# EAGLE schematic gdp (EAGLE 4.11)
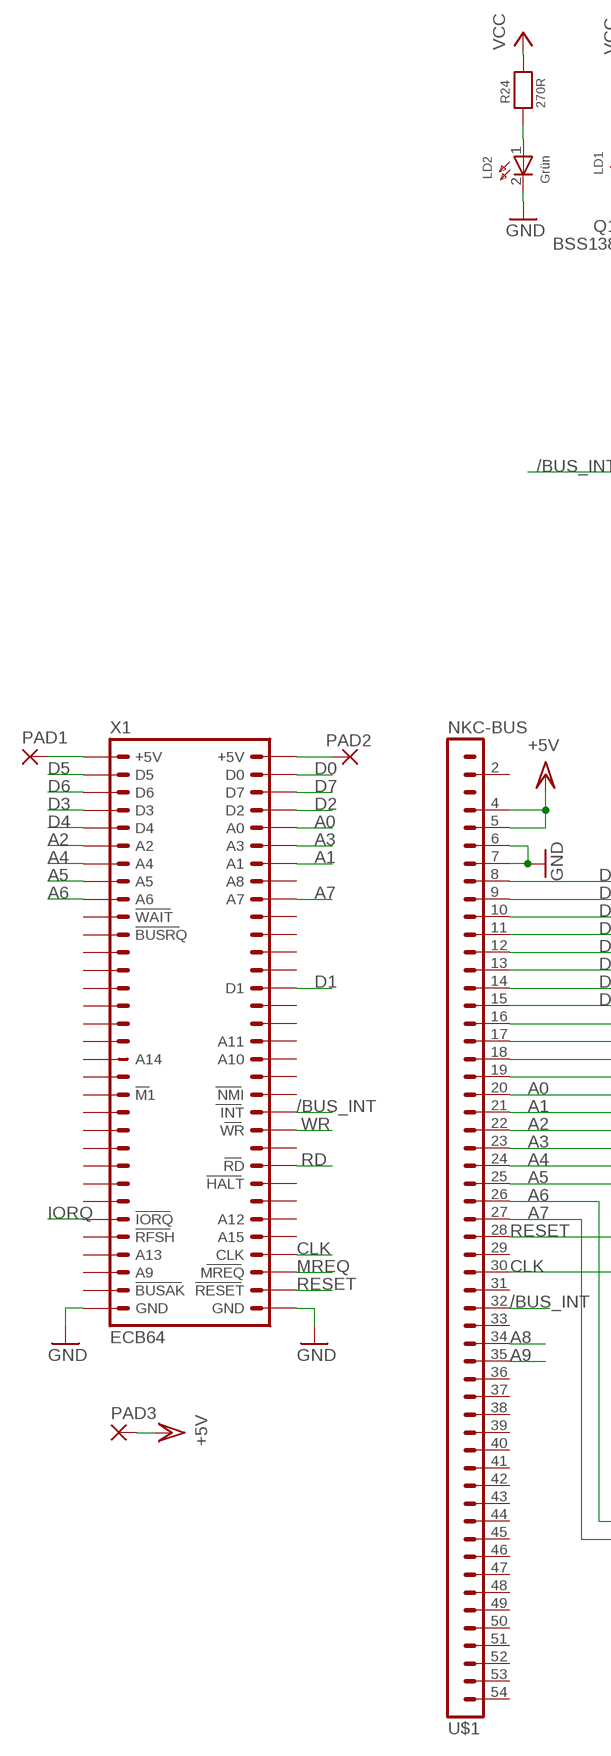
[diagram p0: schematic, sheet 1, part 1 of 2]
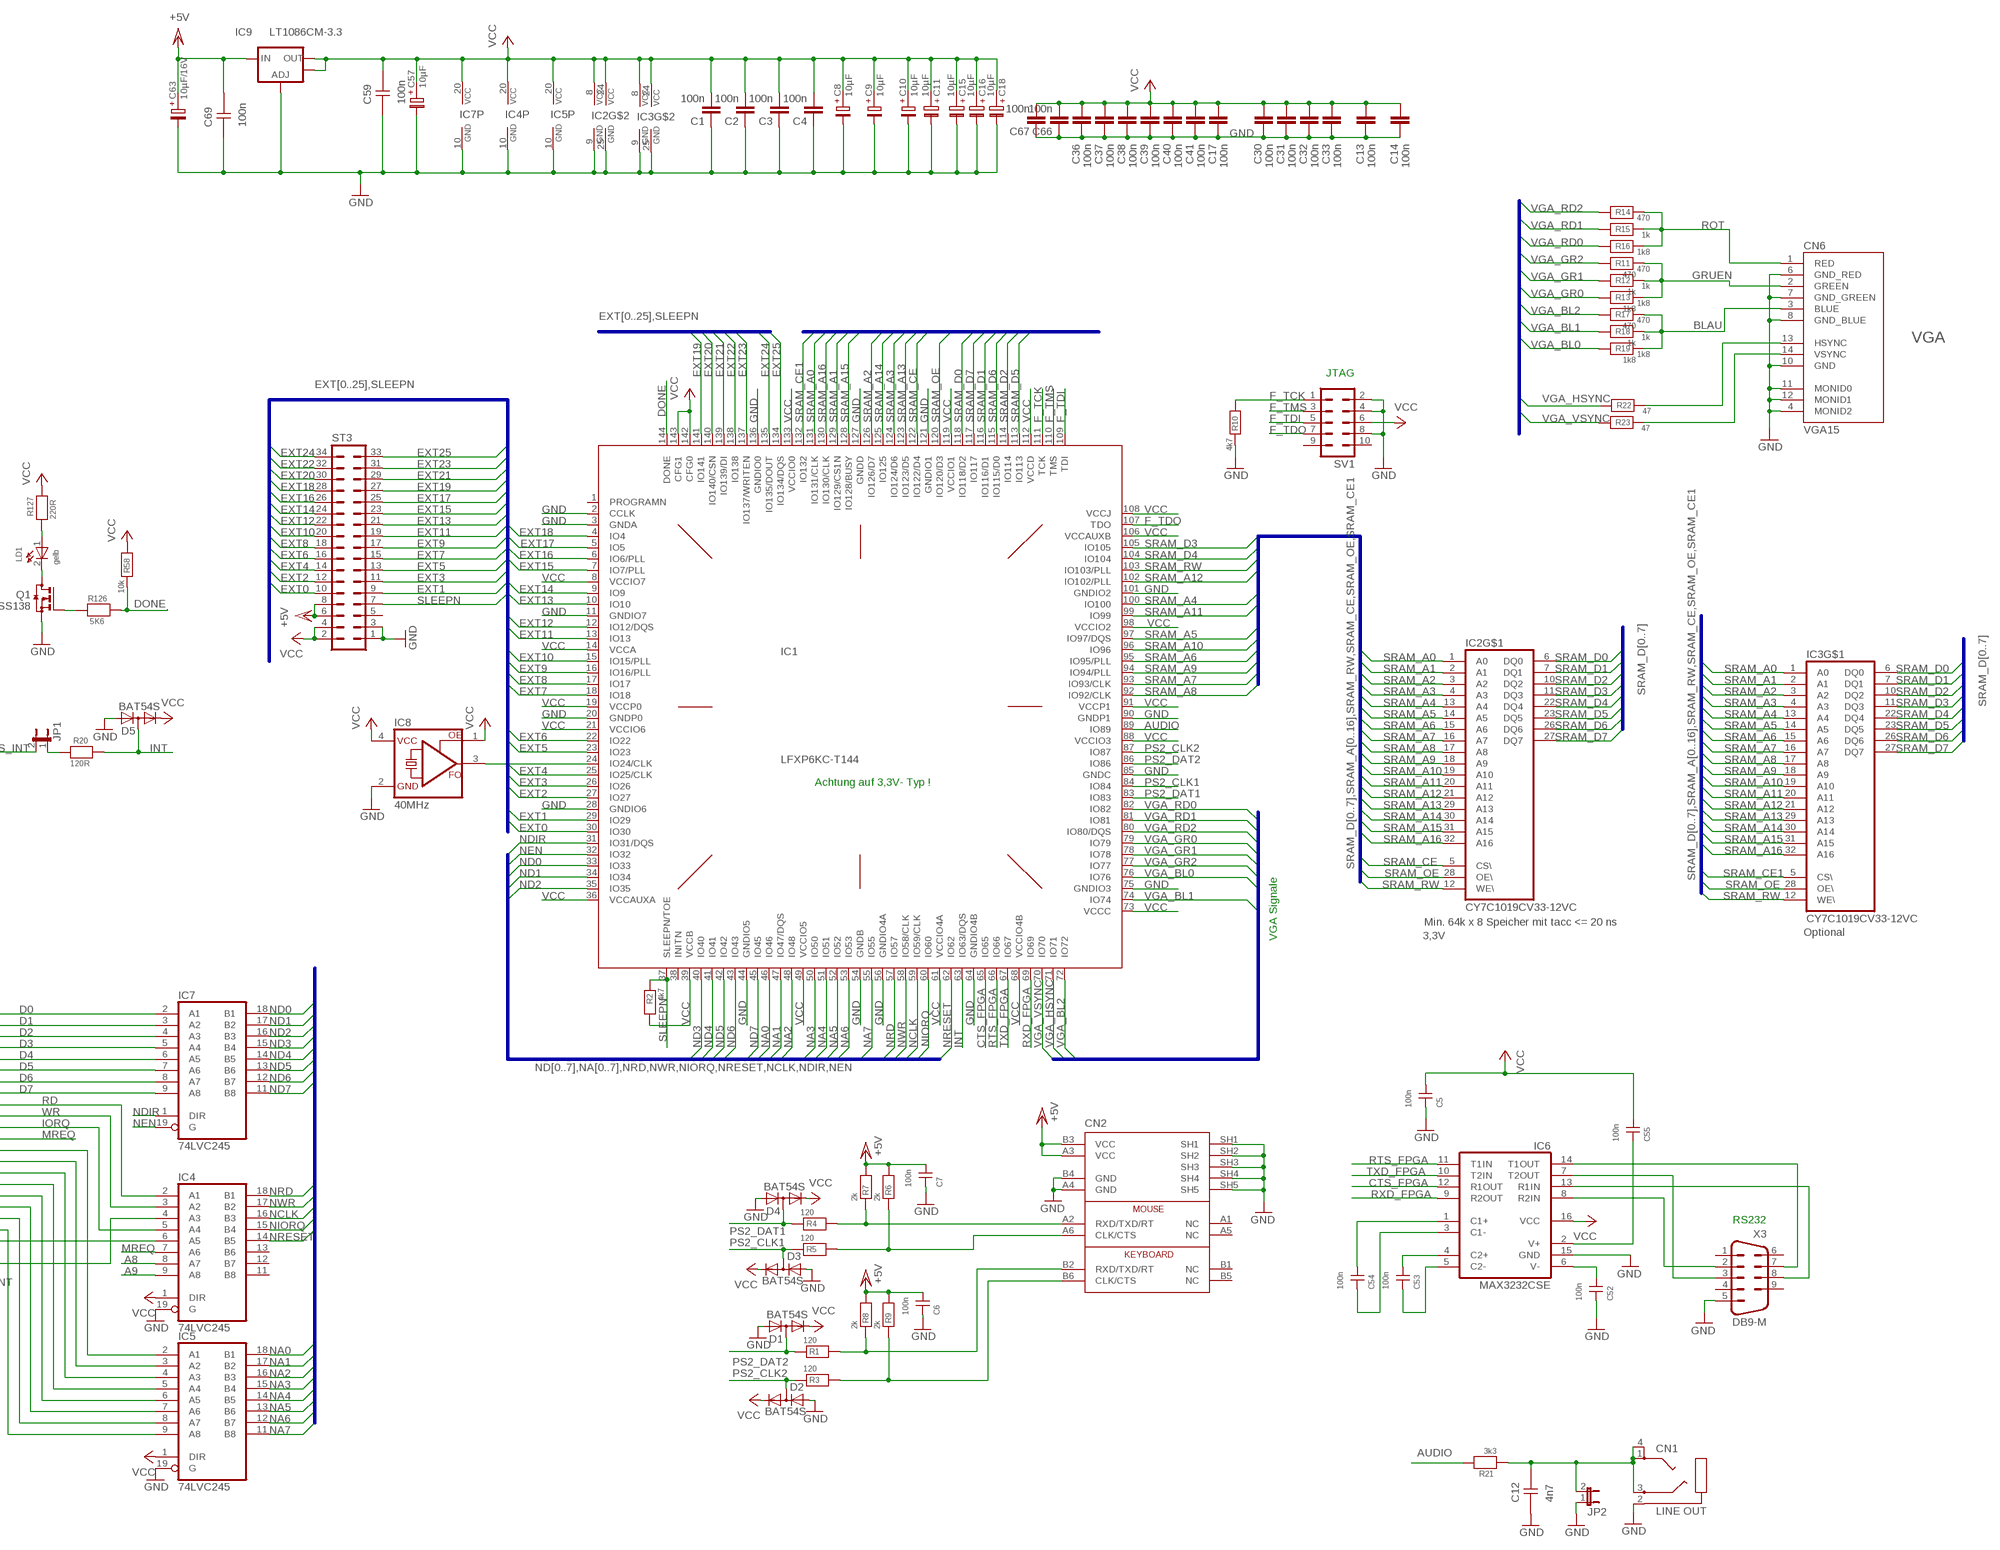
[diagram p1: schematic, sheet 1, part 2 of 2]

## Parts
C1  100n  C-EUC0805K  [C0805K]
C2  100n  C-EUC0805K  [C0805K]
C3  100n  C-EUC0805K  [C0805K]
C4  100n  C-EUC0805K  [C0805K]
C5  100n  CAP0805  [0805]
C6  100n  CAP0805  [0805]
C7  100n  CAP0805  [0805]
C8  10µF  CAPP6032  [TANT_B]
C9  10µF  CAPP6032  [TANT_B]
C10  10µF  CAPP6032  [TANT_B]
C11  10µF  CAPP6032  [TANT_B]
C12  4n7  CAP1206  [0805]
C13  100n  C-EUC0805K  [C0805K]
C14  100n  C-EUC0805K  [C0805K]
C15  10µF  CAPP6032  [TANT_B]
C16  10µF  CAPP6032  [TANT_B]
C17  100n  C-EUC0805K  [C0805K]
C18  10µF  CAPP6032  [TANT_B]
C30  100n  C-EUC0805K  [C0805K]
C31  100n  C-EUC0805K  [C0805K]
C32  100n  C-EUC0805K  [C0805K]
C33  100n  C-EUC0805K  [C0805K]
C36  100n  C-EUC0805K  [C0805K]
C37  100n  C-EUC0805K  [C0805K]
C38  100n  C-EUC0805K  [C0805K]
C39  100n  C-EUC0805K  [C0805K]
C40  100n  C-EUC0805K  [C0805K]
C41  100n  C-EUC0805K  [C0805K]
C52  100n  CAP0805  [0805]
C53  100n  CAP0805  [0805]
C54  100n  CAP0805  [0805]
C55  100n  CAP0805  [0805]
C57  10µF  CAPP6032  [TANT_B]
C59  100n  CAP1206  [0805]
C63  10µF/16V  CAPP6032@2  [TANT_C]
C66  100n  C-EUC0805K  [C0805K]
C67  100n  C-EUC0805K  [C0805K]
C69  100n  CAP1206  [0805]
CN1  LINE OUT  BUCHSE3,5MM  [KLINKE3,5]
CN2  MINIDIN_6POL_DOUBLE  [MINIDIN_6POL_DOUBLE]
CN6  VGA15  VGA15_2  [D-HD15F2]
D1  BAT54S  BAS70-04  [SOT23]
D2  BAT54S  BAS70-04  [SOT23]
D3  BAT54S  BAS70-04  [SOT23]
D4  BAT54S  BAS70-04  [SOT23]
D5  BAT54S  BAS70-04  [SOT23]
IC1  LFXP6KC-T144  [TQFP144]
IC2  CY7C1019CV33-12VC  CY7C1019B  [SOJ32/4]
IC3  CY7C1019CV33-12VC  CY7C1019B  [SOJ32/4]
IC4  74LVC245  74AC245DW  [SO20W]
IC5  74LVC245  74AC245DW  [SO20W]
IC6  MAX3232CSE  MAX3232CWE  [SO16L]
IC7  74LVC245  74AC245DW  [SO20W]
IC8  40MHz  SMDOSZI  [CRYSTAL]
IC9  LT1086CM-3.3  LT1086CM  [3LEAD_DD]
JP1  JP1E  [JP1]
JP2  JP1E  [JP1]
LD1  gelb  LED0603  [0603LED]
LD2  Grün  LED0603  [0603LED]
PAD1  SMD2  [SMD2]
PAD2  SMD2  [SMD2]
PAD3  SMD2  [SMD2]
Q1  BSS138  BSS123  [SOT23]
R1  120  REU0805  [0805]
R2  4k7  REU0805  [0805]
R3  120  REU0805  [0805]
R4  120  REU0805  [0805]
R5  120  REU0805  [0805]
R6  2k  REU0805  [0805]
R7  2k  REU0805  [0805]
R8  2k  REU0805  [0805]
R9  2k  REU0805  [0805]
R10  4k7  REU0805  [0805]
R11  470  REU0805  [0805]
R12  1k  REU0805  [0805]
R13  1k8  REU0805  [0805]
R14  470  REU0805  [0805]
R15  1k  REU0805  [0805]
R16  1k8  REU0805  [0805]
R17  470  REU0805  [0805]
R18  1k  REU0805  [0805]
R19  1k8  REU0805  [0805]
R20  120R  REU0805  [0805]
R21  3k3  REU0805  [0805]
R22  47  REU0805  [0805]
R23  47  REU0805  [0805]
R24  270R  REU0805  [0805]
R58  10k  REU0805  [0805]
R126  5K6  REU0805  [0805]
R127  220R  REU0805  [0805]
ST3  MA17-2  [MA17-2]
SV1  MA05-2  [MA05-2]
U$1  NKC-BUS  [NKC-BUS]
X1  ECB64  [ML64ECB]
X3  DB9-M  M09HP  [M09HP]

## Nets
/BUS_INT: JP1.2 U$1.32 X1.INT
A0: IC5.2(A1) U$1.20 X1.A0
A1: IC5.3(A2) U$1.21 X1.A1
A2: IC5.4(A3) U$1.22 X1.A2
A3: IC5.5(A4) U$1.23 X1.A3
A4: IC5.6(A5) U$1.24 X1.A4
A5: IC5.7(A6) U$1.25 X1.A5
A6: IC5.8(A7) U$1.26 X1.A6
A7: IC5.9(A8) U$1.27 X1.A7
A8: IC4.8(A7) U$1.34
A9: IC4.9(A8) U$1.35
AUDIO: IC1.89(IO89) R21.2
BLAU: CN6.3(BLUE) R17.1 R18.1 R19.1
CLK: IC4.4(A3) U$1.30 X1.CLK
CTS_FPGA: IC1.65(IO65) IC6.12(R1OUT)
D0: IC7.2(A1) U$1.8 X1.D0
D1: IC7.3(A2) U$1.9 X1.D1
D2: IC7.4(A3) U$1.10 X1.D2
D3: IC7.5(A4) U$1.11 X1.D3
D4: IC7.6(A5) U$1.12 X1.D4
D5: IC7.7(A6) U$1.13 X1.D5
D6: IC7.8(A7) U$1.14 X1.D6
D7: IC7.9(A8) U$1.15 X1.D7
DONE: IC1.144(DONE) R58.1 R126.1
EXT0: IC1.30(IO30) ST3.10
EXT1: IC1.29(IO29) ST3.9
EXT2: IC1.27(IO27) ST3.12
EXT3: IC1.26(IO26) ST3.11
EXT4: IC1.25(IO25/CLK) ST3.14
EXT5: IC1.23(IO23) ST3.13
EXT6: IC1.22(IO22) ST3.16
EXT7: IC1.18(IO18) ST3.15
EXT8: IC1.17(IO17) ST3.18
EXT9: IC1.16(IO16/PLL) ST3.17
EXT10: IC1.15(IO15/PLL) ST3.20
EXT11: IC1.13(IO13) ST3.19
EXT12: IC1.12(IO12/DQS) ST3.22
EXT13: IC1.10(IO10) ST3.21
EXT14: IC1.9(IO9) ST3.24
EXT15: IC1.7(IO7/PLL) ST3.23
EXT16: IC1.6(IO6/PLL) ST3.26
EXT17: IC1.5(IO5) ST3.25
EXT18: IC1.4(IO4) ST3.28
EXT19: IC1.141(IO141) ST3.27
EXT20: IC1.140(IO140/CSN) ST3.30
EXT21: IC1.139(IO139/DI) ST3.29
EXT22: IC1.138(IO138) ST3.32
EXT23: IC1.137(IO137/WRITEN) ST3.31
EXT24: IC1.135(IO135/DOUT) ST3.34
EXT25: IC1.134(IO134/DQS) ST3.33
F_TCK: IC1.111(TCK) R10.2 SV1.1
F_TDI: IC1.109(TDI) SV1.5
F_TDO: IC1.107(TDO) SV1.7
F_TMS: IC1.110(TMS) SV1.3
GND: C1.1 C2.1 C3.1 C4.1 C5.1 C6.1 C7.1 C8.2(-) C9.2(-) C10.2(-) C11.2(-) C12.1 C13.1 C14.1 C15.2(-) C16.2(-) C17.1 C18.2(-) C30.1 C31.1 C32.1 C33.1 C36.1 C37.1 C38.1 C39.1 C40.1 C41.1 C52.1 C57.2(-) C59.1 C63.2(-) C66.1 C67.1 C69.1 CN1.2(GND) CN2.A4(GND) CN2.B4(GND) CN2.SH1 CN2.SH2 CN2.SH3 CN2.SH4 CN2.SH5 CN6.4(MONID2) CN6.6(GND_RED) CN6.7(GND_GREEN) CN6.8(GND_BLUE) CN6.10(GND) CN6.11(MONID0) CN6.12(MONID1) D1.1(A) D2.1(A) D3.1(A) D4.1(A) D5.1(A) IC1.2(CCLK) IC1.3(GNDA) IC1.11(GNDIO7) IC1.20(GNDP0) IC1.28(GNDIO6) IC1.44(GNDIO5) IC1.54(GNDB) IC1.56(GNDIO4A) IC1.64(GNDIO4B) IC1.75(GNDIO3) IC1.85(GNDC) IC1.90(GNDP1) IC1.101(GNDIO2) IC1.121(GNDIO1) IC1.127(GNDD) IC1.136(GNDIO0) IC2.9(GND) IC2.25(GND1) IC3.9(GND) IC3.25(GND1) IC4.10(GND) IC4.19(G) IC5.10(GND) IC5.19(G) IC6.15(GND) IC7.10(GND) IC8.2(GND) IC9.1(ADJ) JP2.1 LD2.2(K) Q1.2(S) R10.1 ST3.1 ST3.3 SV1.2 SV1.4 SV1.8 U$1.6 U$1.7 X1.GND X1.GND@1(GND) X3.5
GRUEN: CN6.2(GREEN) R11.1 R12.1 R13.1
INT: D5.3(AC) IC1.63(IO63/DQS) R20.2
IORQ: IC4.5(A4) U$1.18 X1.IORQ
MREQ: IC4.7(A6) U$1.19 X1.MREQ
N$1: IC1.24(IO24/CLK) IC8.3(FO)
N$2: PAD1.1(P) X1.+5V
N$3: LD2.1(A) R24.1
N$4: IC6.14(T1OUT) X3.7
N$5: IC6.13(R1IN) X3.8
N$7: CN2.A2(RXD/TXD/RT) R4.2 R7.1
N$8: C54.2 IC6.1(C1+)
N$9: CN2.A6(CLK/CTS) R5.2 R6.1
N$10: CN2.B2(RXD/TXD/RT) R1.2 R8.1
N$11: CN2.B6(CLK/CTS) R3.2 R9.1
N$18: PAD2.1(P) X1.+5V@1(+5V)
N$20: C54.1 IC6.3(C1-)
N$22: C53.2 IC6.4(C2+)
N$23: C53.1 IC6.5(C2-)
N$27: JP1.1 R20.1
N$28: C12.2 CN1.1(LEFT1) CN1.3(RIGHT) CN1.4(LEFT2) JP2.2 R21.1
N$30: CN6.13(HSYNC) R22.1
N$36: CN6.14(VSYNC) R23.1
N$80: LD1.1(A) R127.1
N$89: LD1.2(K) Q1.3(D)
N$92: Q1.1(G) R126.2
NA0: IC1.46(IO46) IC5.18(B1)
NA1: IC1.47(IO47/DQS) IC5.17(B2)
NA2: IC1.48(IO48) IC5.16(B3)
NA3: IC1.50(IO50) IC5.15(B4)
NA4: IC1.51(IO51) IC5.14(B5)
NA5: IC1.52(IO52) IC5.13(B6)
NA6: IC1.53(IO53) IC5.12(B7)
NA7: IC1.55(IO55) IC5.11(B8)
NCLK: IC1.59(IO59/CLK) IC4.16(B3)
ND0: IC1.33(IO33) IC7.18(B1)
ND1: IC1.34(IO34) IC7.17(B2)
ND2: IC1.35(IO35) IC7.16(B3)
ND3: IC1.40(IO40) IC7.15(B4)
ND4: IC1.41(IO41) IC7.14(B5)
ND5: IC1.42(IO42) IC7.13(B6)
ND6: IC1.43(IO43) IC7.12(B7)
ND7: IC1.45(IO45) IC7.11(B8)
NDIR: IC1.31(IO31/DQS) IC7.1(DIR)
NEN: IC1.32(IO32) IC7.19(G)
NIORQ: IC1.60(IO60) IC4.15(B4)
NRD: IC1.57(IO57) IC4.18(B1)
NRESET: IC1.62(IO62) IC4.14(B5)
NWR: IC1.58(IO58/CLK) IC4.17(B2)
PS2_CLK1: D3.3(AC) IC1.84(IO84) R5.1
PS2_CLK2: D2.3(AC) IC1.87(IO87) R3.1
PS2_DAT1: D4.3(AC) IC1.83(IO83) R4.1
PS2_DAT2: D1.3(AC) IC1.86(IO86) R1.1
RD: IC4.2(A1) U$1.16 X1.RD
RESET: IC4.6(A5) U$1.28 X1.RESET
ROT: CN6.1(RED) R14.1 R15.1 R16.1
RTS_FPGA: IC1.66(IO66) IC6.11(T1IN)
RXD: IC6.8(R2IN) X3.2
RXD_FPGA: IC1.69(IO69) IC6.9(R2OUT)
SLEEPN: IC1.37(SLEEPN/TOE) R2.1 ST3.7
SRAM_A0: IC1.131(IO131/CLK) IC2.1(A0) IC3.1(A0)
SRAM_A1: IC1.129(IO129/CS1N) IC2.2(A1) IC3.2(A1)
SRAM_A2: IC1.126(IO126/D7) IC2.3(A2) IC3.3(A2)
SRAM_A3: IC1.124(IO124/D6) IC2.4(A3) IC3.4(A3)
SRAM_A4: IC1.100(IO100) IC2.13(A4) IC3.13(A4)
SRAM_A5: IC1.97(IO97/DQS) IC2.14(A5) IC3.14(A5)
SRAM_A6: IC1.95(IO95/PLL) IC2.15(A6) IC3.15(A6)
SRAM_A7: IC1.93(IO93/CLK) IC2.16(A7) IC3.16(A7)
SRAM_A8: IC1.92(IO92/CLK) IC2.17(A8) IC3.17(A8)
SRAM_A9: IC1.94(IO94/PLL) IC2.18(A9) IC3.18(A9)
SRAM_A10: IC1.96(IO96) IC2.19(A10) IC3.19(A10)
SRAM_A11: IC1.99(IO99) IC2.20(A11) IC3.20(A11)
SRAM_A12: IC1.102(IO102/PLL) IC2.21(A12) IC3.21(A12)
SRAM_A13: IC1.123(IO123/D5) IC2.29(A13) IC3.29(A13)
SRAM_A14: IC1.125(IO125) IC2.30(A14) IC3.30(A14)
SRAM_A15: IC1.128(IO128/BUSY) IC2.31(A15) IC3.31(A15)
SRAM_A16: IC1.130(IO130/CLK) IC2.32(A16) IC3.32(A16)
SRAM_CE: IC1.122(IO122/D4) IC2.5(CS\)
SRAM_CE1: IC1.132(IO132) IC3.5(CS\)
SRAM_D0: IC1.118(IO118/D2) IC2.6(DQ0) IC3.6(DQ0)
SRAM_D1: IC1.116(IO116/D1) IC2.7(DQ1) IC3.7(DQ1)
SRAM_D2: IC1.114(IO114) IC2.10(DQ2) IC3.10(DQ2)
SRAM_D3: IC1.105(IO105) IC2.11(DQ3) IC3.11(DQ3)
SRAM_D4: IC1.104(IO104) IC2.22(DQ4) IC3.22(DQ4)
SRAM_D5: IC1.113(IO113) IC2.23(DQ5) IC3.23(DQ5)
SRAM_D6: IC1.115(IO115/D0) IC2.26(DQ6) IC3.26(DQ6)
SRAM_D7: IC1.117(IO117) IC2.27(DQ7) IC3.27(DQ7)
SRAM_OE: IC1.120(IO120/D3) IC2.28(OE\) IC3.28(OE\)
SRAM_RW: IC1.103(IO103/PLL) IC2.12(WE\) IC3.12(WE\)
TXD: IC6.7(T2OUT) X3.3
TXD_FPGA: IC1.67(IO67) IC6.10(T2IN)
V+_IC1: C55.1 IC6.2(V+)
V-_IC1: C52.2 IC6.6(V-)
VCC: C1.2 C2.2 C3.2 C4.2 C5.2 C8.1(+) C9.1(+) C10.1(+) C11.1(+) C13.2 C14.2 C15.1(+) C16.1(+) C17.2 C18.1(+) C30.2 C31.2 C32.2 C33.2 C36.2 C37.2 C38.2 C39.2 C40.2 C41.2 C55.2 C57.1(+) C59.2 C66.2 C67.2 D1.2(C) D2.2(C) D3.2(C) D4.2(C) D5.2(C) IC1.8(VCCIO7) IC1.14(VCCA) IC1.19(VCCP0) IC1.21(VCCIO6) IC1.36(VCCAUXA) IC1.39(VCCB) IC1.49(VCCIO5) IC1.61(VCCIO4A) IC1.68(VCCIO4B) IC1.73(VCCC) IC1.88(VCCIO3) IC1.91(VCCP1) IC1.98(VCCIO2) IC1.106(VCCAUXB) IC1.108(VCCJ) IC1.112(VCCD) IC1.119(VCCIO1) IC1.133(VCCIO0) IC1.142(CFG0) IC1.143(CFG1) IC2.8(VCC) IC2.24(VCC3) IC3.8(VCC) IC3.24(VCC3) IC4.1(DIR) IC4.20(VCC) IC5.1(DIR) IC5.20(VCC) IC6.16(VCC) IC7.20(VCC) IC8.1(OE) IC8.4(VCC) IC9.2(OUT) IC9.2@1(OUT1) R2.2 R24.2 R58.2 R127.2 ST3.2 ST3.4 SV1.6
VCC/2: C6.2 C7.2 C63.1(+) C69.2 CN2.A3(VCC) CN2.B3(VCC) IC9.3(IN) PAD3.1(P) R6.2 R7.2 R8.2 R9.2 ST3.6 ST3.8 U$1.4 U$1.5 ; supply symbol labelled +5V
VGA_BL0: IC1.76(IO76) R19.2
VGA_BL1: IC1.74(IO74) R18.2
VGA_BL2: IC1.72(IO72) R17.2
VGA_GR0: IC1.79(IO79) R13.2
VGA_GR1: IC1.78(IO78) R12.2
VGA_GR2: IC1.77(IO77) R11.2
VGA_HSYNC: IC1.71(IO71) R22.2
VGA_RD0: IC1.82(IO82) R16.2
VGA_RD1: IC1.81(IO81) R15.2
VGA_RD2: IC1.80(IO80/DQS) R14.2
VGA_VSYNC: IC1.70(IO70) R23.2
WR: IC4.3(A2) U$1.17 X1.WR
Unconnected: CN2.A1(NC) CN2.A5(NC) CN2.B1(NC) CN2.B5(NC) CN6.5(NC) CN6.9(NC) CN6.15(NC) IC1.1(PROGRAMN) IC1.38(INITN) IC4.11(B8) IC4.12(B7) IC4.13(B6) ST3.5 SV1.9 SV1.10 U$1.2 U$1.29 U$1.31 U$1.33 U$1.36 U$1.37 U$1.38 U$1.39 U$1.40 U$1.41 U$1.42 U$1.43 U$1.44 U$1.45 U$1.46 U$1.47 U$1.48 U$1.49 U$1.50 U$1.51 U$1.52 U$1.53 U$1.54 X1.10C X1.11C X1.12A X1.12C X1.13A X1.13C X1.14A X1.15A X1.15C X1.16A X1.16C X1.17A X1.19A X1.19C X1.21A X1.22A X1.23A X1.23C X1.24A X1.25A X1.26A X1.26C X1.A8 X1.A9 X1.A10 X1.A11 X1.A12 X1.A13 X1.A14 X1.A15 X1.BUSAK X1.BUSRQ X1.HALT X1.M1 X1.NMI X1.RFSH X1.WAIT X3.1 X3.4 X3.6 X3.9

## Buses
SRAM_D[0..7],SRAM_A[0..16],SRAM_RW,SRAM_CE,SRAM_OE,SRAM_CE1
SRAM_D[0..7]
VGA_RD[0..2],VGA_BL[0..2],VGA_GR[0..2],VGA_VSYNC,VGA_HSYNC
ND[0..7],NA[0..7],NRD,NWR,NIORQ,NRESET,NCLK,NDIR,NEN
EXT[0..25],SLEEPN

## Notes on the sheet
- VGA
- JTAG
- Achtung auf 3,3V- Typ !
- VGA Signale
- Min. 64k x 8 Speicher mit tacc <= 20 ns
- Optional
- 3,3V
- RS232

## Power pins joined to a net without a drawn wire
AGND1: CN6.PAD1(AGND1)
AGND2: CN6.PAD2(AGND2)

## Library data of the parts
C1-C4 C13 C14 C17 C30-C33 C36-C41 C66 C67 = rcl:C-EU: CAPACITOR, European symbol
C5-C7 C52-C55 = DISCRSMD:CAP0805
C8-C11 C15 C16 C18 C57 = DiscrSMD@3:CAPP6032
C12 C59 C69 = DiscrSMD@2:CAP1206
C63 = DiscrSMD@3:CAPP6032@2
CN1 = con-audio:BUCHSE3,5MM: 3,5mm Klinkenbuchse
CN2 = Con-pc2:MINIDIN_6POL_DOUBLE
CN6 = CON-PC:VGA15_2
D1-D5 = diode:BAS70-04: Silicon Schottky Diodes General-purpose diode for high-speed switching
IC1 = lattice:LFXP6KC-T144
IC2 IC3 = cy7c1009b:CY7C1019B
IC4 IC5 IC7 = 74xx-eu:74*245: Octal BUS TRANSCEIVER, 3-state
IC6 = Sandbox2:MAX3232CWE
IC8 = mylib:SMDOSZI
IC9 = V-REG2:LT1086CM
JP1 JP2 = jumper:JP1E: JUMPER
LD1 LD2 = DISCRSMD:LED0603
PAD1-PAD3 = wirepad:SMD2: SMD PAD
Q1 = transistor-small-signal:BSS123: N-CHANNEL MOS FET
R1-R24 R58 R126 R127 = DISCRSMD:REU0805
ST3 = con-lstb:MA17-2: PIN HEADER
SV1 = con-lstb:MA05-2: PIN HEADER
U$1 = con-lstb:NKC-BUS
X1 = con-vg:ECB64: CONNECTOR male, 64 pins, block, type C, rows AC, grid 5.08 mm
X3 = con-subd:M09: HARTING SUB-D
